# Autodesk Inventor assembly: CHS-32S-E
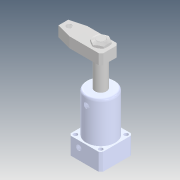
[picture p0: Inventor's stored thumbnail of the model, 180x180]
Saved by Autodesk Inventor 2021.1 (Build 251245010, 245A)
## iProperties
Created: 2020-02
Part Number: CHS-32S-E
Description: STEP AP214
Document SubType Name: Assembly
Designer: user
Title: chs-32s-e_asm.STEP
Revision Number: ÈÎºÎ
Sending System: SolidWorks 2016
Preprocessor: SwSTEP 2.0
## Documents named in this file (5)
- D:\Vault_2016\Projekty\Clamptek\Hydraulic\CHS\CHS-32\Inventor\CHS-32S-E\CHS-32S-E.iam
- D:\Vault_2016\Projekty\Clamptek\Hydraulic\CHS\CHS-32\Inventor\CHS-32S-E\CHS-32-03-E_1.ipt
- D:\Vault_2016\Projekty\Clamptek\Hydraulic\CHS\CHS-32\Inventor\CHS-32S-E\CHS-32S-02-E.ipt
- D:\Vault_2016\Projekty\Clamptek\Hydraulic\CHS\CHS-32\Inventor\CHS-32S-E\CHS-32S-01_1.ipt
- D:\Vault_2016\Projekty\Clamptek\Hydraulic\CHS\CHS-32\Inventor\CHS-32S-E\M16_1.ipt
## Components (4 placed, 4 different names)
1. CHS-32-03-E_1_1
2. CHS-32S-02-E_2
3. CHS-32S-01_1_3
4. M16_1_4
